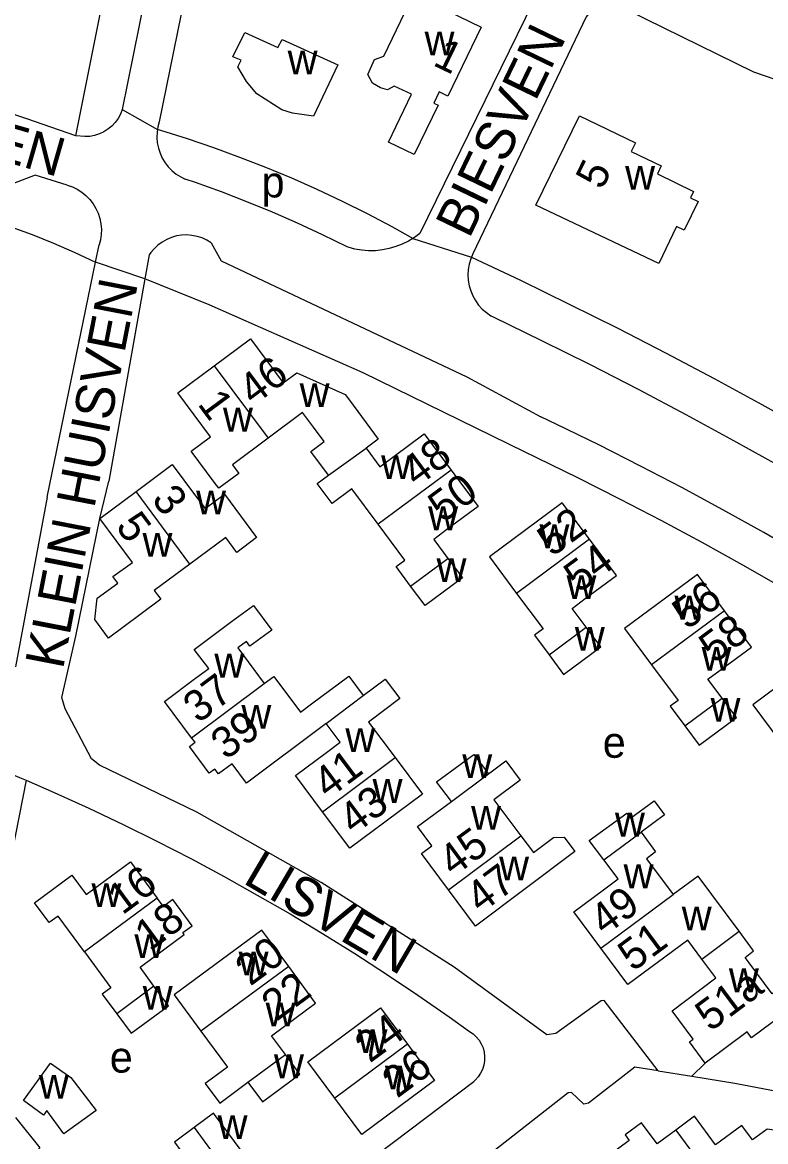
# Model space of a CAD drawing. Extents: x 162667 to 164645, y 379003 to 382150.
# Drawn here: x 163689.7 to 163785.6, y 381379.4 to 381524 of the extents above; entities that cross this region are included whole.
import ezdxf

# ---------------------------------------------------------------- set-up
doc = ezdxf.new("R2010")
doc.units = 0
for name, color, linetype in [('BLT_Basislijn', 7, 'Continuous'), ('BLT_Bebouwing', 7, 'Continuous'), ('BLT_Centroide', 7, 'Continuous'), ('BLT_Huisnummer', 7, 'Continuous'), ('BLT_Onderverdeling_panden', 7, 'Continuous'), ('BLT_Straatnaam', 7, 'Continuous'), ('BLT_Vlakafsluiter', 7, 'Continuous')]:
    doc.layers.add(name, color=color, linetype=linetype)

msp = doc.modelspace()

# ---------------------------------------------------------------- linework, layer by layer
at = {"layer": 'BLT_Basislijn'}
for p, q in [((163696.6, 381509.36), (163713.54, 381595.13)), ((163718.99, 381594.07), (163702.57, 381512.75)), ((163722.86, 381587.97), (163707.35, 381511.17)), ((163699.14, 381493.05), (163699.6, 381495.27)), ((163706.06, 381493.98), (163705.5, 381490.88)), ((163747.85, 381494.11), (163747.67, 381493.69)), ((163692.9, 381462.68), (163699.14, 381493.05)), ((163705.5, 381490.88), (163700.85, 381464.74)), ((163699.66, 381459.92), (163700.85, 381464.74)), ((163692.9, 381462.68), (163688.79, 381440.79)), ((163690.17, 381426.11), (163683.11, 381390.4)), ((163776.11, 381387.88), (163777.85, 381389.56)), ((163771.79, 381388.58), (163776.11, 381387.88)), ((163709.7, 381358.29), (163747.99, 381387.22))]:
    msp.add_line(p, q, dxfattribs=at)
for points in [[(163753.72, 381573.21), (163752.28, 381570.2), (163750.45, 381562.73), (163746.95, 381545.18), (163747.71, 381540.76), (163749.54, 381536.19), (163750.6, 381534.97), (163753.2, 381533.44), (163755.02, 381532.68), (163756.55, 381530.39), (163756.7, 381528.86), (163741.02, 381496.77)], [(163822.54, 381550.84), (163813.71, 381539.08), (163799.99, 381520.32), (163798.46, 381518.8), (163796.02, 381517.12), (163791.15, 381516.36), (163786.88, 381516.66), (163784.14, 381517.58), (163765.54, 381526.73), (163763.56, 381526.12), (163762.49, 381524.75), (163747.85, 381494.11)], [(163695.47, 381503.01), (163691.34, 381504.3), (163687.99, 381503.01), (163646.95, 381515.66), (163645.92, 381517.47), (163633.79, 381520.31), (163631.98, 381519.02), (163602.3, 381523.93), (163579.33, 381526.77), (163559.71, 381528.58), (163557.39, 381530.9), (163548.1, 381530.64)], [(163696.6, 381509.36), (163690.24, 381511.58), (163684.5, 381513.49), (163678.73, 381515.33), (163672.94, 381517.09), (163667.12, 381518.77), (163661.29, 381520.38), (163655.43, 381521.91), (163649.56, 381523.36), (163648.24, 381523.67)], [(163702.57, 381512.75), (163702.33, 381512.16), (163702.03, 381511.6), (163701.65, 381511.09), (163701.22, 381510.62), (163700.73, 381510.22), (163700.19, 381509.88), (163699.62, 381509.61), (163699.01, 381509.41), (163698.39, 381509.3), (163697.75, 381509.26), (163696.6, 381509.36)], [(163707.35, 381511.17), (163707.17, 381510.51), (163707.12, 381510.18)], [(163707.12, 381510.18), (163707.07, 381509.83), (163707.04, 381509.14), (163707.1, 381508.45), (163707.24, 381507.77), (163707.45, 381507.12), (163707.74, 381506.49), (163708.1, 381505.9), (163708.52, 381505.36), (163709, 381504.86), (163709.54, 381504.43), (163710.13, 381504.07), (163710.7, 381503.79)], [(163740.11, 381496.12), (163737.42, 381497.61), (163734.24, 381499.28), (163731.01, 381500.89), (163727.75, 381502.42), (163724.46, 381503.88), (163721.13, 381505.26), (163717.77, 381506.57), (163714.39, 381507.81), (163710.98, 381508.97), (163707.55, 381510.05), (163707.12, 381510.18)], [(163731.61, 381495.01), (163728.43, 381496.58), (163725.21, 381498.08), (163721.96, 381499.5), (163718.68, 381500.85), (163715.38, 381502.13), (163712.04, 381503.33), (163710.7, 381503.79)], [(163695.47, 381503.01), (163696.13, 381502.78), (163696.76, 381502.47), (163697.35, 381502.09), (163697.89, 381501.65), (163698.38, 381501.15), (163698.81, 381500.6), (163699.17, 381500), (163699.47, 381499.36), (163699.68, 381498.7), (163699.82, 381498.01), (163699.89, 381497.31), (163699.87, 381496.61), (163699.77, 381495.92), (163699.6, 381495.27)], [(163685.39, 381498.58), (163688.18, 381497.63), (163690.94, 381496.6), (163693.68, 381495.5), (163696.38, 381494.33), (163699.14, 381493.05)], [(163714.06, 381495.53), (163713.49, 381495.88), (163712.88, 381496.17), (163712.24, 381496.37), (163711.58, 381496.51), (163710.91, 381496.56), (163710.24, 381496.53), (163709.58, 381496.43), (163708.93, 381496.24), (163708.31, 381495.98), (163707.73, 381495.65), (163707.19, 381495.25), (163706.7, 381494.79), (163706.27, 381494.28), (163706.06, 381493.98)], [(163741.02, 381496.77), (163740.3, 381496.23), (163740.11, 381496.12)], [(163714.06, 381495.53), (163715.35, 381493.2), (163747.09, 381478.23), (163756.64, 381473.06)], [(163740.11, 381496.12), (163739.54, 381495.77), (163738.74, 381495.37), (163737.9, 381495.05), (163737.05, 381494.8), (163736.17, 381494.63), (163735.28, 381494.53), (163734.39, 381494.52), (163733.49, 381494.59), (163732.61, 381494.74), (163731.75, 381494.97), (163731.61, 381495.01)], [(163747.67, 381493.69), (163747.58, 381493.46), (163747.38, 381492.79), (163747.26, 381492.1), (163747.21, 381491.4), (163747.25, 381490.7), (163747.37, 381490.01), (163747.57, 381489.34), (163747.84, 381488.69), (163748.18, 381488.08), (163748.59, 381487.51), (163749.06, 381486.99), (163749.59, 381486.53), (163750.17, 381486.13), (163750.45, 381485.97)], [(163747.67, 381493.69), (163753.99, 381490.71), (163760.3, 381487.64), (163766.57, 381484.51), (163772.8, 381481.3), (163778.99, 381478.02), (163785.15, 381474.67), (163791.27, 381471.25), (163797.35, 381467.77), (163803.39, 381464.21), (163809.39, 381460.58), (163815.35, 381456.89), (163821.26, 381453.12), (163827.13, 381449.3), (163832.96, 381445.4), (163838.74, 381441.44), (163844.48, 381437.41), (163849.33, 381433.93)], [(163754.5, 381468.54), (163733.67, 381478.74), (163713.8, 381487.52), (163705.5, 381490.88)], [(163750.45, 381485.97), (163756.73, 381482.93), (163762.98, 381479.81), (163769.18, 381476.62), (163775.36, 381473.36), (163781.49, 381470.03), (163787.59, 381466.64), (163793.65, 381463.17), (163799.67, 381459.63), (163805.64, 381456.02), (163811.58, 381452.35), (163817.47, 381448.6), (163823.32, 381444.79), (163829.12, 381440.91), (163834.89, 381436.97), (163840.6, 381432.96), (163841.27, 381432.48)], [(163830.97, 381428.65), (163826.09, 381432.19), (163821.16, 381435.66), (163816.18, 381439.07), (163811.16, 381442.42), (163806.09, 381445.69), (163800.98, 381448.9), (163795.83, 381452.04), (163790.64, 381455.12), (163785.41, 381458.12), (163780.14, 381461.05), (163774.83, 381463.92), (163769.48, 381466.71), (163764.1, 381469.43), (163758.68, 381472.09), (163756.64, 381473.06)], [(163828.01, 381424.62), (163823.15, 381428.14), (163818.25, 381431.59), (163813.3, 381434.98), (163808.3, 381438.31), (163803.27, 381441.57), (163798.18, 381444.76), (163793.06, 381447.88), (163787.9, 381450.93), (163782.69, 381453.91), (163777.45, 381456.83), (163772.16, 381459.67), (163766.84, 381462.45), (163761.49, 381465.15), (163756.1, 381467.78), (163754.5, 381468.54)], [(163771.79, 381388.58), (163764.82, 381397.66), (163764.4, 381397.62), (163758.58, 381393.41), (163757.42, 381393.22), (163745.42, 381401.97), (163728.24, 381412.89), (163712.2, 381421.99), (163699.64, 381428.05), (163698.6, 381428.88), (163695.22, 381435.33), (163694.78, 381436.79), (163696.59, 381444.72), (163699.66, 381459.92)], [(163685.47, 381428.09), (163689.31, 381426.49), (163690.17, 381426.11)], [(163690.17, 381426.11), (163693.8, 381424.53), (163698.26, 381422.51), (163702.68, 381420.41), (163707.06, 381418.23), (163711.42, 381415.99), (163715.73, 381413.68), (163720, 381411.29), (163724.24, 381408.84), (163728.43, 381406.32), (163732.59, 381403.72), (163736.7, 381401.07), (163740.76, 381398.34), (163744.78, 381395.55), (163747.41, 381393.67)], [(163747.41, 381393.67), (163747.87, 381393.35), (163748.29, 381392.97), (163748.65, 381392.54), (163748.94, 381392.05), (163749.16, 381391.53), (163749.3, 381390.99), (163749.37, 381390.43), (163749.36, 381389.86), (163749.26, 381389.31), (163749.09, 381388.77), (163748.85, 381388.26), (163748.53, 381387.79), (163748.16, 381387.37), (163747.99, 381387.22)], [(163771.79, 381388.58), (163768.77, 381389.05), (163762.79, 381384.39), (163762.17, 381384.27), (163760.58, 381385.77), (163760.14, 381385.74), (163738.74, 381368.93), (163716.92, 381352.35), (163716.45, 381351.71), (163715.11, 381347.06), (163727.05, 381331.16)], [(163776.11, 381387.88), (163781.69, 381386.98), (163793.85, 381384.64), (163795.09, 381383.04)], [(163688.79, 381382.53), (163691.92, 381378.62), (163689.32, 381375.65)]]:
    msp.add_lwpolyline(points, dxfattribs=at)
at = {"layer": 'BLT_Bebouwing'}
msp.add_line((163699.66, 381459.92), (163704.35, 381463.4), dxfattribs=at)
for points in [[(163736.37, 381519.66), (163741.32, 381529.98), (163744.28, 381528.53), (163743.17, 381526.21), (163748.91, 381523.4), (163744.61, 381514.5), (163743.49, 381515.04), (163742.8, 381513.6), (163743.35, 381513.34), (163740.29, 381506.94), (163736.96, 381508.54), (163739.91, 381514.73), (163737.69, 381515.8), (163736.81, 381515.33), (163735.9, 381515.56), (163734.9, 381516.17), (163734.3, 381517.31), (163735.13, 381519.22), (163736.37, 381519.66)], [(163718.4, 381522.71), (163722.68, 381520.77), (163723.23, 381521.82), (163730.4, 381518.55), (163727.26, 381511.9), (163724.54, 381512.28), (163723.17, 381512.74), (163719.97, 381514.79), (163718.6, 381516.4), (163717.49, 381518.26), (163717.92, 381519.16), (163716.87, 381519.59), (163718.4, 381522.71)], [(163761.6, 381511.95), (163768.83, 381508.47), (163768.29, 381507.34), (163772.16, 381505.48), (163771.67, 381504.45), (163776.35, 381502.19), (163775.95, 381501.37), (163776.93, 381500.9), (163775.15, 381497.19), (163774.15, 381497.67), (163771.85, 381492.89), (163755.98, 381500.41), (163761.6, 381511.95)], [(163714.45, 381479.67), (163719.13, 381483.15), (163723.37, 381477.44), (163725.11, 381478.73), (163731.35, 381475.97), (163731.91, 381475.22)], [(163721.41, 381470.3), (163716.8, 381466.86), (163717.63, 381465.75), (163715.06, 381463.84), (163714.46, 381464.64), (163711.47, 381468.65), (163713.97, 381470.5), (163709.76, 381476.18), (163714.45, 381479.67)], [(163731.91, 381475.22), (163735.63, 381470.19), (163734.06, 381469.02)], [(163727.26, 381471.75), (163725.86, 381473.62), (163721.41, 381470.3)], [(163729.2, 381465.53), (163726.92, 381468.59), (163728.65, 381469.88), (163727.26, 381471.75)], [(163734.06, 381469.02), (163735.84, 381466.61), (163741.56, 381470.85), (163745.04, 381466.16)], [(163704.35, 381463.4), (163709.04, 381466.89), (163712.03, 381462.88), (163713.27, 381461.21), (163715.76, 381463.07), (163719.93, 381457.46), (163717.37, 381455.56), (163715.93, 381457.49), (163711.32, 381454.05)], [(163745.04, 381466.16), (163748.52, 381461.47), (163744.5, 381458.49), (163742.81, 381457.24), (163744.63, 381454.78)], [(163735.64, 381459.18), (163732.23, 381463.78), (163729.67, 381461.88), (163727.75, 381464.46), (163729.2, 381465.53)], [(163762.89, 381457.25), (163759.4, 381461.94), (163750.01, 381454.96), (163753.5, 381450.26)], [(163711.32, 381454.05), (163706.71, 381450.61), (163707.54, 381449.49), (163704.83, 381447.47), (163700.82, 381444.48), (163699.04, 381446.87), (163699.34, 381449.63), (163702, 381451.57), (163701.37, 381452.42), (163703.88, 381454.25), (163699.66, 381459.92)], [(163739.81, 381451.21), (163737.95, 381453.72), (163739.07, 381454.56), (163735.64, 381459.18)], [(163762.49, 381445.88), (163760.68, 381448.32), (163762.37, 381449.58), (163766.38, 381452.56), (163762.89, 381457.25)], [(163744.63, 381454.78), (163746.5, 381452.25), (163741.69, 381448.68), (163739.81, 381451.21)], [(163780.33, 381448.02), (163776.84, 381452.71), (163767.45, 381445.73), (163770.93, 381441.04)], [(163753.5, 381450.26), (163756.92, 381445.66), (163755.82, 381444.84), (163757.68, 381442.32)], [(163711.52, 381431.61), (163708.03, 381436.3), (163712.04, 381439.29), (163713.74, 381440.56), (163711.87, 381443.03), (163716.69, 381446.61), (163719.52, 381448.71), (163721.89, 381445.51), (163719.06, 381443.42), (163718.6, 381444.04), (163717.48, 381443.21), (163720.9, 381438.6)], [(163780.02, 381436.72), (163778.21, 381439.17), (163779.8, 381440.35), (163783.81, 381443.33), (163780.33, 381448.02)], [(163757.68, 381442.32), (163759.57, 381439.78), (163764.37, 381443.35), (163762.49, 381445.88)], [(163796.86, 381438.15), (163793.37, 381442.83), (163783.98, 381435.86), (163787.47, 381431.16)], [(163770.93, 381441.04), (163774.35, 381436.44), (163773.33, 381435.68), (163775.2, 381433.15)], [(163720.9, 381438.6), (163722.14, 381439.53), (163725.57, 381434.92), (163727.01, 381435.99), (163731.82, 381439.58), (163733.7, 381437.06)], [(163733.7, 381437.06), (163736.54, 381439.19), (163738.43, 381436.66), (163734.39, 381433.64)], [(163775.2, 381433.15), (163777.08, 381430.63), (163781.89, 381434.21), (163780.02, 381436.72)], [(163728.9, 381433.46), (163718.62, 381425.73), (163716.76, 381428.23), (163715.01, 381426.93), (163714.53, 381427.57), (163713.81, 381427.03), (163711.24, 381430.48), (163711.97, 381431.02), (163711.52, 381431.61)], [(163728.45, 381422.03), (163724.94, 381426.71), (163728.95, 381429.7), (163730.72, 381431.02), (163728.9, 381433.46)], [(163734.39, 381433.64), (163737.82, 381429.04)], [(163737.82, 381429.04), (163741.33, 381424.33), (163731.95, 381417.34), (163728.45, 381422.03)], [(163745.07, 381423.36), (163743.16, 381425.91), (163747.99, 381429.44), (163749.88, 381426.96)], [(163749.88, 381426.96), (163752.11, 381428.61), (163753.96, 381426.11), (163750.57, 381423.58), (163754.05, 381418.94)], [(163744.69, 381411.97), (163741.2, 381416.65), (163742.55, 381417.66), (163740.7, 381420.14), (163745.07, 381423.36)], [(163764.75, 381415.83), (163762.88, 381418.35), (163767.71, 381421.88), (163768.2, 381421.22), (163771.24, 381423.47), (163772.6, 381421.64), (163769.56, 381419.41)], [(163754.05, 381418.94), (163755.67, 381416.78), (163758.27, 381418.72), (163759.63, 381418.77), (163761.02, 381416.92), (163748.18, 381407.28), (163744.69, 381411.97)], [(163769.56, 381419.41), (163771.45, 381416.88), (163770.26, 381415.98), (163773.73, 381411.34)], [(163691.26, 381410.28), (163696.07, 381413.86), (163697.91, 381411.37), (163703.62, 381415.59), (163707.1, 381410.89)], [(163764.38, 381404.41), (163760.9, 381409.11), (163764.9, 381412.11), (163766.59, 381413.37), (163764.75, 381415.83)], [(163782.23, 381406.6), (163776.92, 381413.71), (163773.73, 381411.34)], [(163697.7, 381403.93), (163694.28, 381408.55), (163693.15, 381407.72), (163691.26, 381410.28)], [(163706.67, 381399.53), (163704.87, 381401.97), (163706.56, 381403.22), (163710.57, 381406.2), (163710.4, 381406.44), (163711.6, 381407.33), (163709.1, 381410.7), (163707.9, 381409.81), (163707.1, 381410.89)], [(163724.07, 381402.04), (163720.59, 381406.73), (163709.28, 381398.39), (163712.74, 381393.69)], [(163788.99, 381396.69), (163787.22, 381399.06), (163786.5, 381398.51), (163783.51, 381402.53), (163783, 381403.22), (163784.1, 381404.1), (163782.23, 381406.6)], [(163777.43, 381403.02), (163775.62, 381405.45), (163767.87, 381399.71), (163764.38, 381404.41)], [(163697.7, 381403.93), (163701.12, 381399.31), (163699.99, 381398.48), (163701.87, 381395.95)], [(163777.85, 381389.56), (163775.82, 381392.34), (163776.29, 381392.68), (163773.57, 381396.35), (163779.24, 381400.59), (163777.43, 381403.02)], [(163723.64, 381390.68), (163721.83, 381393.12), (163723.52, 381394.37), (163727.54, 381397.34), (163724.07, 381402.04)], [(163701.87, 381395.95), (163703.73, 381393.43), (163708.55, 381396.99), (163706.67, 381399.53)], [(163730.02, 381385.03), (163726.52, 381389.74), (163735.91, 381396.71), (163739.4, 381392.01)], [(163788.99, 381396.69), (163783.84, 381392.84), (163783.27, 381393.6), (163777.85, 381389.56)], [(163712.74, 381393.69), (163716.16, 381389.06), (163714.04, 381387.49), (163713.3, 381386.94), (163715.18, 381384.4), (163718.81, 381387.1)], [(163718.81, 381387.1), (163720.68, 381384.58), (163725.51, 381388.15), (163723.64, 381390.68)], [(163739.4, 381392.01), (163742.9, 381387.31), (163733.49, 381380.36), (163730.02, 381385.03)], [(163715.41, 381376.42), (163717.94, 381378.28), (163714.37, 381383.12), (163711.84, 381381.25)], [(163778.2, 381375.29), (163782.46, 381369.51), (163786.13, 381372.21), (163785.42, 381373.18), (163787.55, 381374.74), (163791.17, 381377.41), (163788.83, 381380.6), (163785.87, 381381.06), (163783.94, 381379.65), (163782.57, 381381.51), (163779.2, 381379.01), (163776.46, 381382.71), (163774.05, 381380.93)], [(163711.84, 381381.25), (163709.3, 381379.38), (163710.14, 381378.25), (163705.5, 381374.83)], [(163774.05, 381380.93), (163771.64, 381379.15), (163769.63, 381381.88), (163767.51, 381380.31), (163768.05, 381379.59), (163764.39, 381376.88)]]:
    msp.add_lwpolyline(points, dxfattribs=at)
msp.add_lwpolyline([(163693.33, 381389.58), (163695.92, 381387.73), (163699.22, 381383.46), (163695.05, 381380.42), (163692.84, 381383.47), (163692.4, 381382.87), (163689.82, 381384.74)], close=True, dxfattribs=at)
at = {"layer": 'BLT_Onderverdeling_panden'}
for p, q in [((163714.45, 381479.67), (163721.41, 381470.3)), ((163729.2, 381465.53), (163734.06, 381469.02)), ((163745.04, 381466.16), (163735.64, 381459.18)), ((163711.32, 381454.05), (163704.35, 381463.4)), ((163762.89, 381457.25), (163753.5, 381450.26)), ((163739.81, 381451.21), (163744.63, 381454.78)), ((163780.33, 381448.02), (163770.93, 381441.04)), ((163757.68, 381442.32), (163762.49, 381445.88)), ((163711.52, 381431.61), (163720.9, 381438.6)), ((163728.9, 381433.46), (163733.7, 381437.06)), ((163775.2, 381433.15), (163780.02, 381436.72)), ((163728.45, 381422.03), (163737.82, 381429.04)), ((163745.07, 381423.36), (163749.88, 381426.96)), ((163744.69, 381411.97), (163754.05, 381418.94)), ((163764.75, 381415.83), (163769.56, 381419.41)), ((163764.38, 381404.41), (163773.73, 381411.34)), ((163707.1, 381410.89), (163697.7, 381403.93)), ((163777.43, 381403.02), (163782.23, 381406.6)), ((163724.07, 381402.04), (163712.74, 381393.69)), ((163706.67, 381399.53), (163701.87, 381395.95)), ((163718.81, 381387.1), (163723.64, 381390.68)), ((163739.4, 381392.01), (163730.02, 381385.03)), ((163711.84, 381381.25), (163715.41, 381376.42)), ((163774.05, 381380.93), (163778.2, 381375.29))]:
    msp.add_line(p, q, dxfattribs=at)
at = {"layer": 'BLT_Vlakafsluiter'}
for p, q in [((163702.57, 381512.75), (163707.12, 381510.18)), ((163740.11, 381496.12), (163747.67, 381493.69)), ((163705.5, 381490.88), (163699.14, 381493.05))]:
    msp.add_line(p, q, dxfattribs=at)

# ---------------------------------------------------------------- texts
at = {"layer": 'BLT_Centroide'}
for s, p in [('w', (163741.61, 381519.77)), ('w', (163723.93, 381517.31)), ('w', (163767.51, 381502.41)), ('p', (163720.56, 381501.41)), ('w', (163725.48, 381474.34)), ('w', (163715.58, 381471.17)), ('w', (163736, 381465.03)), ('w', (163712.11, 381460.47)), ('w', (163742.08, 381458.42)), ('w', (163756.45, 381456.09)), ('w', (163705.19, 381455)), ('w', (163743.16, 381451.72)), ('w', (163759.94, 381449.53)), ('w', (163773.88, 381446.88)), ('w', (163761.02, 381442.84)), ('w', (163777.38, 381440.28)), ('w', (163714.47, 381439.39)), ('w', (163717.96, 381432.78)), ('w', (163778.54, 381433.69)), ('w', (163731.38, 381429.77)), ('e', (163764.62, 381429.02)), ('w', (163746.48, 381426.41)), ('w', (163734.9, 381423.19)), ('w', (163747.62, 381419.72)), ('w', (163766.2, 381418.84)), ('w', (163751.24, 381413.19)), ('w', (163767.31, 381412.17)), ('w', (163698.6, 381409.75)), ('w', (163774.82, 381406.72)), ('w', (163704.14, 381403.16)), ('w', (163717.6, 381400.91)), ('w', (163780.91, 381398.73)), ('w', (163705.22, 381396.47)), ('w', (163721.09, 381394.31)), ('w', (163732.96, 381390.88)), ('e', (163700.96, 381388.35)), ('w', (163722.17, 381387.62)), ('w', (163736.48, 381386.19)), ('w', (163691.81, 381384.98)), ('w', (163714.89, 381379.77))]:
    msp.add_text(s, height=4, dxfattribs=at).set_placement(p)
at = {"layer": 'BLT_Huisnummer'}
for s, rotation, p in [('1', 334.2233, (163742.55, 381518.55)), ('5', 64.2826, (163764.55, 381502.27)), ('46', 36.6925, (163719.52, 381474.42)), ('1', 306.5375, (163712.21, 381474.72)), ('48', 36.5348, (163740.6, 381463.89)), ('50', 36.5348, (163744, 381459.28)), ('3', 306.6591, (163706.26, 381462.38)), ('5', 306.6591, (163701.62, 381458.88)), ('52', 36.5348, (163758.09, 381454.89)), ('54', 36.5348, (163761.53, 381450.21)), ('56', 36.5348, (163775.52, 381445.47)), ('58', 36.5348, (163778.98, 381441.08)), ('37', 36.7232, (163712.38, 381433.38)), ('39', 36.6337, (163715.95, 381428.65)), ('41', 36.7034, (163729.16, 381423.61)), ('43', 36.7034, (163732.47, 381418.97)), ('45', 36.1885, (163745.33, 381413.56)), ('47', 36.6543, (163748.87, 381408.82)), ('16', 36.5077, (163702.59, 381408.63)), ('49', 36.223, (163764.86, 381405.93)), ('18', 36.5077, (163706.12, 381403.93)), ('51', 36.5253, (163768.51, 381401.31)), ('20', 36.5077, (163719.1, 381399.44)), ('22', 36.5077, (163722.48, 381394.89)), ('51a', 36.6932, (163778.5, 381393.55)), ('24', 36.5077, (163734.54, 381389.51)), ('26', 36.5077, (163738.07, 381384.96))]:
    msp.add_text(s, height=4, rotation=rotation, dxfattribs=at).set_placement(p)
at = {"layer": 'BLT_Straatnaam'}
for s, rotation, p in [('BIESVEN', 64.2649, (163747.37, 381495.97)), ('DIEPMEERVEN', 343.9757, (163647.48, 381517.48)), ('KLEIN HUISVEN', 79.0116, (163694.91, 381440.34)), ('LISVEN', 329.5396, (163718.01, 381412.91))]:
    msp.add_text(s, height=5, rotation=rotation, dxfattribs=at).set_placement(p)

doc.saveas('drawing.dxf')
